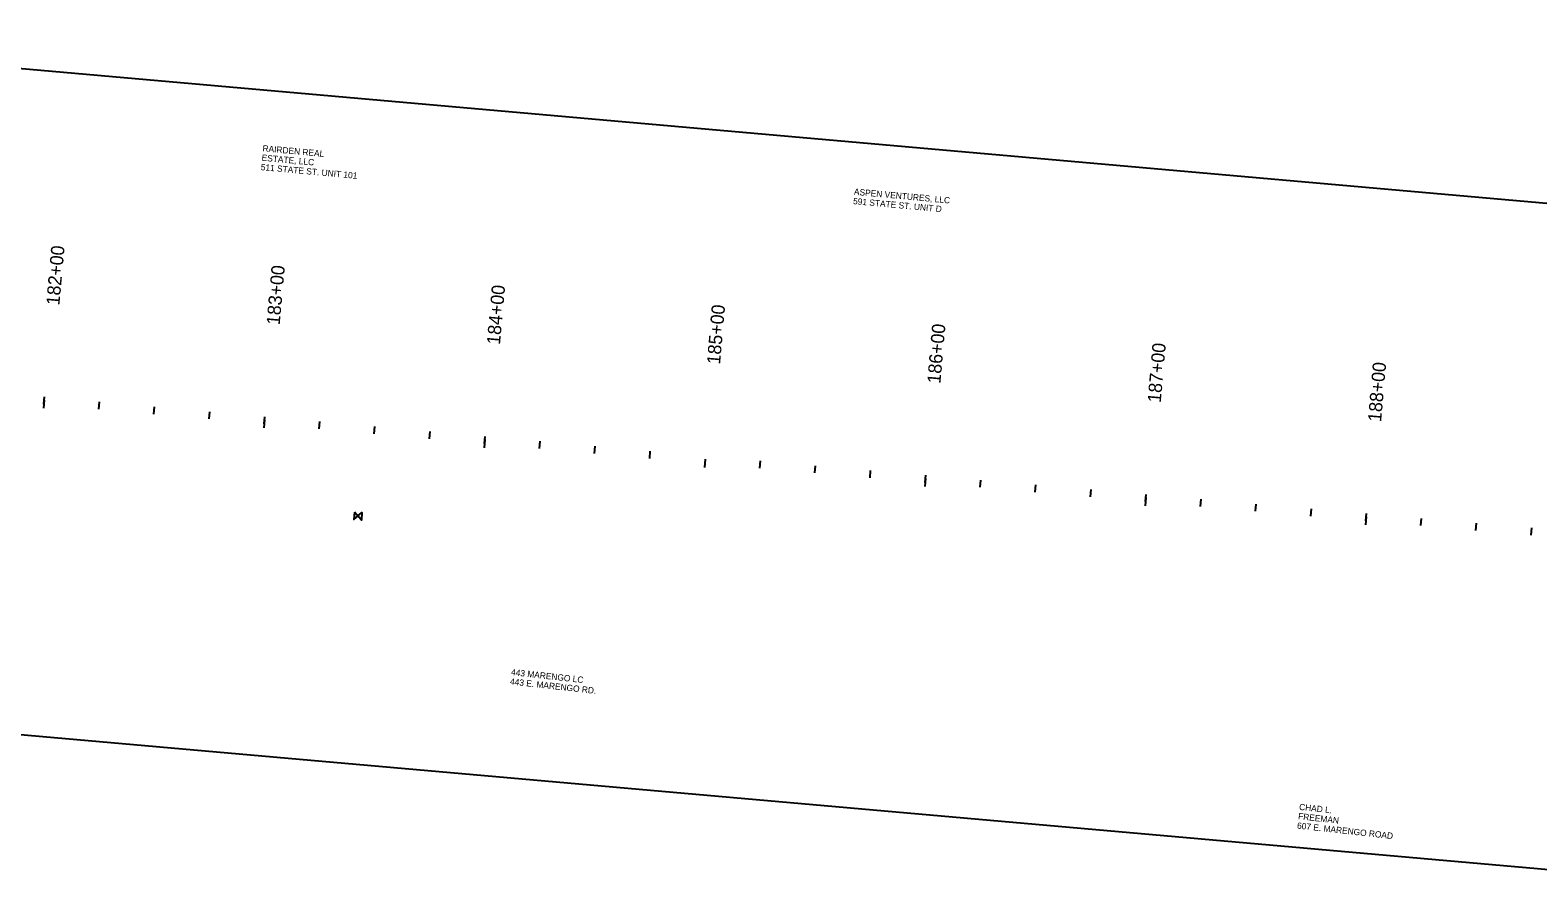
# Model space of a CAD drawing. Extents: x 20499788 to 20505371, y 7953467 to 7954209.
# Drawn here: x 20501902 to 20502583, y 7953669 to 7954051 of the extents above; entities that cross this region are included whole.
import ezdxf

# ---------------------------------------------------------------- set-up
doc = ezdxf.new("R2010")
doc.units = 0
for name, color, linetype in [('NamedBoundary', 7, 'Continuous'), ('Text', 7, 'Continuous'), ('TextAlignmentLrg', 7, 'Continuous'), ('TextAlignmentSml', 7, 'Continuous'), ('Utility-Water - alignment', 7, 'Continuous')]:
    doc.layers.add(name, color=color, linetype=linetype)

msp = doc.modelspace()

# ---------------------------------------------------------------- linework, layer by layer
at = {"layer": 'NamedBoundary'}
msp.add_lwpolyline([(20501700.08, 7954051), (20501673.66, 7953752.17), (20502610.5, 7953669.34), (20502636.92, 7953968.17)], close=True, dxfattribs=at)
at = {"layer": 'TextAlignmentLrg'}
for p, q in [((20501907.98, 7953881.8), (20501908.28, 7953885.06)), ((20502007.59, 7953872.88), (20502007.88, 7953876.14)), ((20502107.19, 7953863.96), (20502107.48, 7953867.23)), ((20502206.95, 7953856.88), (20502206.63, 7953853.23)), ((20502306.41, 7953846.39), (20502306.7, 7953849.65)), ((20502406.04, 7953837.72), (20502406.32, 7953840.98)), ((20502505.66, 7953829.05), (20502505.94, 7953832.31))]:
    msp.add_line(p, q, dxfattribs=at)
at = {"layer": 'TextAlignmentSml'}
for p, q in [((20501908.15, 7953883.63), (20501907.82, 7953879.97)), ((20501932.88, 7953879.57), (20501933.18, 7953882.83)), ((20501957.79, 7953877.34), (20501958.08, 7953880.6)), ((20501982.69, 7953875.11), (20501982.98, 7953878.37)), ((20502007.75, 7953874.71), (20502007.42, 7953871.05)), ((20502032.49, 7953870.65), (20502032.78, 7953873.91)), ((20502057.39, 7953868.42), (20502057.68, 7953871.69)), ((20502082.29, 7953866.19), (20502082.58, 7953869.46)), ((20502107.35, 7953865.79), (20502107.02, 7953862.13)), ((20502132.09, 7953861.73), (20502132.38, 7953865)), ((20502156.99, 7953859.5), (20502157.28, 7953862.77)), ((20502181.89, 7953857.27), (20502182.18, 7953860.54)), ((20502206.95, 7953856.88), (20502206.63, 7953853.23)), ((20502231.7, 7953852.89), (20502231.98, 7953856.15)), ((20502256.6, 7953850.72), (20502256.89, 7953853.98)), ((20502281.51, 7953848.55), (20502281.79, 7953851.82)), ((20502306.57, 7953848.21), (20502306.25, 7953844.56)), ((20502331.32, 7953844.22), (20502331.6, 7953847.48)), ((20502356.23, 7953842.05), (20502356.51, 7953845.31)), ((20502381.13, 7953839.88), (20502381.42, 7953843.15)), ((20502406.2, 7953839.54), (20502405.88, 7953835.89)), ((20502430.94, 7953835.55), (20502431.23, 7953838.81)), ((20502455.85, 7953833.38), (20502456.13, 7953836.64)), ((20502480.75, 7953831.21), (20502481.04, 7953834.48)), ((20502505.82, 7953830.88), (20502505.5, 7953827.22)), ((20502530.57, 7953826.88), (20502530.85, 7953830.14)), ((20502555.47, 7953824.71), (20502555.76, 7953827.98)), ((20502580.38, 7953822.54), (20502580.66, 7953825.81))]:
    msp.add_line(p, q, dxfattribs=at)
at = {"layer": 'Utility-Water - alignment'}
msp.add_lwpolyline([(20502048.48, 7953832.99), (20502048.21, 7953829.67), (20502051.8, 7953832.73), (20502051.54, 7953829.4)], close=True, dxfattribs=at)

# ---------------------------------------------------------------- texts
at = {"layer": 'Text'}
for s, height, rotation, p in [('ESTATE, LLC', 2.8346, 354.76449, (20502006.36, 7953991.95)), ('RAIRDEN REAL ', 2.8346, 354.76449, (20502006.75, 7953996.18)), ('511 STATE ST. UNIT 101', 2.8346, 354.76449, (20502005.97, 7953987.71)), ('ASPEN VENTURES, LLC', 2.8346, 354.76449, (20502274.15, 7953976.56)), ('591 STATE ST. UNIT D', 2.8346, 354.76449, (20502273.76, 7953972.32)), ('443 MARENGO LC', 2.8346, 353.70825, (20502119.11, 7953759.25)), ('443 E. MARENGO RD.', 2.8346, 353.70825, (20502118.64, 7953755.02)), ('CHAD L.', 2.835, 353.70825, (20502475.4, 7953698.29)), ('607 E. MARENGO ROAD', 2.8346, 353.70825, (20502474.47, 7953689.84)), ('FREEMAN', 2.835, 353.70825, (20502474.94, 7953694.07))]:
    msp.add_text(s, height=height, rotation=rotation, dxfattribs=at).set_placement(p)
at = {"layer": 'TextAlignmentLrg'}
msp.add_text('185+00', height=6.012, rotation=85.02642, dxfattribs=at).set_placement((20502213.69, 7953899.63))
at = {"layer": 'TextAlignmentSml'}
for s, rotation, p in [('182+00', 84.88337, (20501914.99, 7953926.35)), ('183+00', 84.88337, (20502014.59, 7953917.43)), ('184+00', 84.88337, (20502114.19, 7953908.52)), ('185+00', 85.02642, (20502213.69, 7953899.63)), ('186+00', 85.02642, (20502313.31, 7953890.96)), ('187+00', 85.02642, (20502412.93, 7953882.29)), ('188+00', 85.02642, (20502512.56, 7953873.62))]:
    msp.add_text(s, height=6.012, rotation=rotation, dxfattribs=at).set_placement(p)

doc.saveas('drawing.dxf')
